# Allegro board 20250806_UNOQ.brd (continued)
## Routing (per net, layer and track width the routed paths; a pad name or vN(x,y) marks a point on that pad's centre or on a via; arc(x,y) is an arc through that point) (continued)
FORCED_USB_BOOT_POL_SEL: length 22.1
  TOP w0.066: R1313.2 R1314.1 22.21,17.64 21.45,18.4 21.45,27.13 21.18,27.4 21.18,28.5 20.77,28.91 20.77,30.77 v2(20.61,30.93)
  S3 w0.064: v2(20.61,30.93) 21.12,30.42 21.51,30.42 22.26,29.67 25.81,29.67 26.01,29.87 26.38,29.87 v2(26.57,29.68)
HPH_L: length 22.8
  TOP w0.15: v2(42.67,16.02) 42.63,15.98 PMIC1.L27
  S3 w0.15: v3(42.39,15.99) 42.65,15.99 v2(42.67,16.02)
  S6 w0.15: v5(42.4,16.3) 42.39,16.29 v3(42.39,15.99)
  BOTTOM w0.15: v5(42.4,16.3) 42.1,16.6 39.15,16.6 38.51,15.96 36.2,15.96 35.52,16.64 33.26,16.64 32.57,15.95 23.61,15.95 23.27,15.61 R2634.2
HPH_L_CONN: length 2.4
  BOTTOM w0.15: R2634.1 23.24,14.25 D26089.2 23.24,13.26 23.49,13 23.49,11.98
HPH_R: length 23.4
  TOP w0.15: v2(42.67,17.07) 42.39,17.07 41.87,16.55 PMIC1.J27
  S3 w0.15: v3(42.37,17.07) 42.67,17.07 v2(42.67,17.07)
  S6 w0.15: v3(42.37,17.07) v5(42.05,17.07)
  BOTTOM w0.15: R2635.2 22.73,15.66 23.38,16.31 32.47,16.31 33.14,16.98 35.6,16.98 36.39,16.19 38.33,16.19 39.02,16.88 41.86,16.88 v5(42.05,17.07)
HPH_R_CONN: length 2.5
  BOTTOM w0.15: 22.22,11.98 22.22,12.75 22.73,13.26 D26090.2 22.73,14.27 R2635.1
HPH_REF: length 27.4
  TOP w0.15: 42.12,16.26 PMIC1.K26
  TOP w0.2: v2(42.67,16.54) 42.4,16.54 42.12,16.26
  S3 w0.2: v2(42.67,16.54) 42.92,16.54 42.93,16.54 v3(42.95,16.54)
  S6 w0.2: v5(42.65,16.54) v3(42.95,16.54)
  BOTTOM w0.2: R2633.2 22,14.59 22,15.98 22.99,16.97 29.66,16.97 30.71,18.02 35.19,18.02 36.67,16.54 38.19,16.54 39.3,17.65 41.8,17.65 ; v5(42.65,16.54) 42.65,17.15
  BOTTOM w0.203: 42.65,17.15 42.15,17.65 41.8,17.65
HPH_REF_CONN: length 2.1
  BOTTOM w0.203: 20.95,11.98 20.95,12.66 21.68,13.39 R2633.1
HS_DET: length 51.5
  TOP w0.1: v2(22.42,8.72) 22.42,7.96 23.05,7.33 47.78,7.33 48.11,7.66 48.11,18.8 46.98,19.93 43.9,19.93 v2(43.81,20.02)
  S3 w0.064: v2(22.42,8.72) v3(22.42,9.16)
  S3 w0.1: v2(43.81,20.02) 43.56,19.76 42.75,19.76 42.09,19.1 41.2,19.1 40.39,18.29 40.39,18.21 v2(40.36,18.19)
  S6 w0.1: v3(22.42,9.16) 19.76,11.82 v5(19.68,11.82)
  BOTTOM w0.1: 19.68,11.98 v5(19.68,11.82)
JTAG_PS_HOLD: length 22
  TOP w0.066: v2(22.79,8.38) 35.02,8.38 R709.2
  S3 w0.064: v3(20.4,2.8) 20.12,3.08 20.12,5.5 22.79,8.17 v2(22.79,8.38)
  S6 w0.064: v5(21.71,2.8) v3(20.4,2.8)
  BOTTOM w0.066: TP1213.1 22.64,2.14 22.37,2.14 v5(21.71,2.8)
LDO1_EN: length 2
  BOTTOM w0.066: SB2801.2 11.68,39.33 R2801.2 11.7,40.05 U2801.1
LDO1_FB: length 3
  BOTTOM w0.203: U2801.6 13.6,41.08 12.83,40.31 R2803.1 13.3,40.01 R2802.2 13.42,40.01 C2803.2
LDO1_PG: length 8.2
  BOTTOM w0.203: U2801.5 14.43,42.32 15.11,42.32 15.11,42.09 15.94,41.26 C2808.1 17.08,41.26 R2810.1 17.44,41.37 17.58,41.51 17.58,44.86 Q2802.1
LDO2_EN: length 1
  BOTTOM w0.066: R2804.2 10.5,32.46 10.52,32.48 U2802.1
LDO2_FB: length 2.8
  BOTTOM w0.066: R2805.2 12.22,31.43 C2807.2 12.23,31.45 R2806.1 12.23,32.7 12.69,33.15 U2802.6
LED_MATRIX_0: length 22.5
  S3 w0.1: v3(13.22,9.1) 15.04,9.1 16.42,7.72 19.01,7.72 v2(19.03,7.74)
  S6 w0.1: v3(13.22,9.1) 13.18,9.14 13.18,9.63 9.32,13.49 9.32,15.95 12.04,18.67 12.04,21.34 v4(12.09,21.39)
  G7 w0.1: v4(12.09,21.39) 12.17,21.39 v5(12.9,22.11)
LED_MATRIX_0_R: length 84
  TOP w0.1: D27091.1 v1(8,10.77) ; v1(8.36,20.36) 8.63,20.36 D27074.2 9.88,21.05 v1(10.04,21.05) ; v1(10.91,26.39) 11.07,26.39 D27057.1 12.91,28.22 D27044.2 13.42,29 ; D27092.2 5.79,37.77 16.02,37.77 D27014.2 17.95,36.89 19.48,35.36 ; 15.39,26.86 15.39,27.03 13.42,29 ; 15.39,26.86 v1(14.91,26.39) ; 15.39,26.86 15.88,27.35 v1(16.04,27.35) ; v1(20.04,10.55) 19.03,9.54 R2711.2 ; 19.48,35.36 D27002.2 ; 19.48,35.36 19.88,35.75 v1(20.04,35.75) ; D27007.1 19.88,23.15 D27008.2 18.91,21.92 D27021.1 17.07,20.09 D27022.2 ; 13.42,29 13.88,29.45 D27043.1 ; v1(18.53,29.88) 18.91,30.26 D27004.2 19.07,30.59 D27003.1
  G2 w0.1: v1(10.04,21.05) 9.47,21.62 9.47,25.41 10.45,26.39 v1(10.91,26.39) ; v1(20.42,31.56) 20.42,35.37 v1(20.04,35.75) ; v1(18.53,29.88) 16.04,27.39 v1(16.04,27.35) ; v1(16.51,20.09) 13.58,23.02 13.58,25.29 14.68,26.39 v1(14.91,26.39) ; v1(8.36,20.36) 6.31,18.31 6.31,12.4 D27091.1 v1(8,10.77) 8.23,11 11.92,11 12.67,10.25 16.48,10.25 16.78,10.55 v1(20.04,10.55)
LED_MATRIX_1: length 25.9
  S3 w0.1: v2(21.85,7.96) 21.25,7.36 16.17,7.36 15.02,8.51 v3(13.77,8.51)
  S6 w0.1: v3(13.77,8.51) 13.77,9.35 9.55,13.56 9.55,15.72 12.29,18.47 12.29,20.8 12.42,20.93 12.42,22.59 v5(12.4,22.61)
LED_MATRIX_1_R: length 74.8
  TOP w0.1: v1(20.04,33.65) D27015.1 17.88,33.65 v1(16.91,32.69) ; v1(14.8,25.06) 14.23,25.06 D27045.1 13.53,24.74 ; v1(18.37,25.85) D27006.2 19.07,26.39 D27005.1 ; v1(10.91,22.19) 11.07,22.19 D27059.1 12.04,23.42 D27046.2 13.07,24.29 13.53,24.74 ; 13.53,24.74 15.51,22.76 15.51,22.63 ; 15.51,22.63 15.07,22.19 D27034.2 ; 15.51,22.63 v1(16.04,23.15) ; v1(20.59,17.83) 20.59,18.4 D27009.1 19.07,17.99 D27010.2 18.04,17.12 D27023.1 17.07,15.89 v1(16.91,15.89) ; v1(10.04,16.85) 9.07,15.89 D27076.2 ; D27094.2 5.88,33.65 D27093.1 6.04,33.65 v1(6.33,33.65)
  G2 w0.1: v1(14.8,25.06) 15.08,25.34 17.19,25.34 17.7,25.85 v1(18.37,25.85) ; v1(10.91,22.19) 10.91,21.07 10.39,20.55 10.39,17.2 v1(10.04,16.85) ; v1(18.91,36.89) 18.91,35.64 20.04,34.51 v1(20.04,33.65) 20.04,27.73 v1(20.4,27.37) ; v1(20.59,17.83) 21.16,17.83 21.85,17.14 v1(21.85,8.92) ; v1(16.91,32.69) 15.74,32.69 15.39,33.04 12.75,33.04 10.44,35.35 8.79,35.35 7.09,33.65 v1(6.33,33.65) ; v1(16.04,23.15) 16.04,20.91 16.8,20.15 16.8,18.86 16.44,18.5 16.44,16.35 v1(16.91,15.89)
LED_MATRIX_2: length 26.1
  S3 w0.1: v2(20.89,7.99) 20.44,7.54 16.3,7.54 15.03,8.81 12.94,8.81 12.73,9.02 v3(12.52,9.02)
  S6 w0.1: v5(12.4,23.11) 12.4,22.97 12.19,22.76 12.19,21.89 11.81,21.51 11.81,20.33 11.79,20.31 11.79,18.8 9.07,16.08 9.07,13.41 12.52,9.96 v3(12.52,9.02)
LED_MATRIX_2_R: length 84
  TOP w0.1: v1(6.45,29.04) D27095.1 5.07,28.49 D27096.2 ; D27011.1 19.07,13.79 D27012.2 18.04,12.92 D27025.1 17.07,11.69 v1(16.91,11.69) ; D27011.1 21.14,15.85 21.14,24.15 D27006.1 20.83,26.04 20.83,28.17 20.04,28.96 D27004.1 19.88,29.45 D27005.2 18.04,29.35 D27017.1 ; D27011.1 21.15,13.64 21.15,9.21 R2702.2 ; D27017.1 17.07,28.49 D27018.2 ; D27017.1 18.04,30.61 18.91,31.48 D27003.2 ; 15.47,18.55 D27036.2 ; 15.47,18.55 15.44,18.55 13.41,20.58 ; 15.47,18.55 15.88,18.95 D27035.1 ; 13.41,20.58 13.88,21.05 D27047.1 ; 13.41,20.58 D27048.2 12.91,19.82 D27061.1 11.88,18.95 v1(10.91,17.99) ; v1(10.04,12.23) D27077.1
  G2 w0.1: v1(10.04,12.23) 10.04,11.55 10.31,11.28 ; v1(6.45,29.04) 7.34,28.15 7.34,22.71 8.91,21.14 8.91,20.39 7.6,19.07 7.6,14.67 9.21,13.06 10.33,13.06 10.91,12.48 ; 12.11,11.28 12.78,10.61 15.31,10.61 16.39,11.69 v1(16.91,11.69) ; 12.11,11.28 10.91,12.48 ; 12.11,11.28 10.31,11.28 ; 10.31,11.28 9.31,11.28 v1(8.91,11.69) ; 10.91,12.48 v1(10.91,17.99)
LED_MATRIX_3: length 28.1
  S3 w0.1: v2(19.95,7.99) 18.46,7.99 18.09,8.36 16.69,8.36 15.19,9.86 12.89,9.86 11.45,11.3 8.46,11.3 v3(8.32,11.16)
  S6 w0.1: v3(8.32,11.16) 8.05,11.43 8.05,12.5 7.85,12.7 7.85,17.04 9.86,19.05 9.86,21.59 11.21,22.94 11.21,23.26 11.35,23.4 v4(11.35,23.47)
  G7 w0.1: v4(11.35,23.47) 11.49,23.61 11.9,23.61 12.04,23.47 12.04,23.45 v5(12.06,23.45)
  BOTTOM w0.1: v5(12.06,23.45) 12.04,23.45 12.04,23.47 MCU1.G5
LED_MATRIX_3_R: length 75.7
  TOP w0.1: D27027.1 15.88,35.75 v1(14.91,34.79) ; D27009.2 19.88,21.05 D27008.1 ; D27008.1 20.8,21.81 20.8,23.62 20.13,24.29 D27007.2 18.04,25.15 D27019.1 ; D27008.1 20.84,20.25 20.84,17.65 D27010.1 19.07,15.89 v1(18.91,15.89) ; D27020.2 17.88,25.25 D27019.1 ; D27098.2 5.07,24.29 v1(6.04,25.25) ; D27019.1 v1(18.84,25.25) ; v1(16.04,14.75) 15.88,14.75 D27038.2 14.91,14.9 13.42,16.39 ; v1(8.04,35.75) 7.88,35.75 D27080.2 ; 13.42,16.39 13.88,16.85 D27049.1 ; 13.42,16.39 D27050.2 12.04,15.02 D27063.1 11.07,13.79 D27064.2 ; R2703.2 19.95,9.03 20.82,9.9 20.82,11.87 v1(20.04,12.65)
  G2 w0.1: v1(6.04,25.25) 6.04,29.25 6.92,30.13 6.92,31.31 5.86,32.37 5.86,34.12 7.49,35.75 v1(8.04,35.75) 10.93,35.75 11.89,34.79 v1(14.91,34.79) 15.26,34.43 16.98,34.43 17.71,33.7 17.71,31.29 19.17,29.83 19.17,25.58 v1(18.84,25.25) ; v1(18.91,15.89) 20.04,14.75 v1(20.04,12.65) 19.03,12.65 16.93,14.75 v1(16.04,14.75)
LED_MATRIX_4: length 24.1
  S3 w0.1: v2(17.21,8.13) 16.61,8.13 15.1,9.64 12.83,9.64 11.43,11.04 10.13,11.04 v3(10.08,10.99)
  S6 w0.1: v5(11.9,24.11) 11.9,23.4 11.56,23.07 11.56,22.8 10.29,21.53 10.29,18.82 8.23,16.76 8.23,12.98 8.84,12.37 8.84,11.66 9.32,11.18 9.89,11.18 v3(10.08,10.99)
LED_MATRIX_4_R: length 81.2
  TOP w0.1: D27018.1 17.88,27.35 ; 17.88,27.35 D27019.2 16.8,26.28 16.8,25.41 v1(17.15,25.06) ; 17.88,27.35 17.04,27.35 16.03,28.36 16.03,28.5 16.91,29.38 D27017.2 ; D27030.2 15.88,31.55 D27029.1 16.04,31.45 D27017.2 ; D27081.1 7.88,31.55 D27082.2 ; D27100.2 5.07,20.09 v1(6.04,21.05) ; 13.54,12.15 D27051.1 ; 13.54,12.15 13.07,11.69 D27052.2 12.04,10.82 D27065.1 ; 13.54,12.15 15.14,10.55 v1(16.04,10.55) 17.21,9.38 R2704.2 ; D27017.2 17.88,31.55 v1(18.04,31.55) ; v1(18.04,35.75) 17.88,35.75 D27015.2
  G2 w0.1: v1(6.04,21.05) 5.76,21.33 5.76,29.77 v1(6.57,30.58) 6.57,30.92 5.51,31.98 5.51,35.14 7.65,37.28 v1(8.9,37.28) 8.92,37.26 v1(12.92,37.26) 15.58,37.26 17.09,35.75 v1(18.04,35.75) 18.51,35.28 18.51,32.02 v1(18.04,31.55) ; v1(17.15,25.06) 18.04,24.17 v1(18.04,23.15) 18.04,22.88 16.66,21.5 16.66,20.69 17.03,20.32 17.03,18.7 16.62,18.29 16.62,16.59 17.19,16.02 18.39,16.02 18.65,16.28 19.32,16.28 20.56,15.04 20.56,12.49 19.76,11.69 v1(18.91,11.69) 18.5,11.28 16.77,11.28 v1(16.04,10.55)
LED_MATRIX_5: length 28.1
  S3 w0.1: v3(10.01,9.73) 10.01,9.92 10.4,10.31 11.86,10.31 12.76,9.41 15,9.41 16.51,7.9 17.99,7.9 v2(18.08,7.99)
  S6 w0.1: v3(10.01,9.73) 10.01,10.24 9.45,10.8 7.66,10.8 7.24,11.22 7.24,12.65 7.47,12.88 7.47,17.22 9.47,19.23 9.47,21.77 10.67,22.96 10.67,23.22 10.67,23.22 10.67,23.27 10.82,23.42 10.87,23.42 v4(10.95,23.5)
  G7 w0.1: v5(11.9,23.11) 11.74,23.27 11.18,23.27 v4(10.95,23.5)
LED_MATRIX_5_R: length 65.9
  TOP w0.1: R2705.2 18.08,10.51 D27026.1 17.99,10.6 v1(17.99,11.7) ; 17.5,14.21 17.07,13.79 v1(16.91,13.79) ; 17.5,14.21 16.15,15.56 16.15,16.05 16.91,16.81 D27023.2 17.07,17.99 17.5,18.42 ; 17.5,14.21 D27024.1 ; D27042.2 13.07,32.69 D27041.1 14.04,33.55 v1(14.91,32.69) 15.07,32.69 D27028.1 16.04,34.69 v1(15.78,34.95) ; v1(8.04,27.35) 7.88,27.35 v1(6.91,26.39) ; v1(12.04,35.75) 11.88,35.75 D27054.2 10.91,34.52 D27067.1 9.88,33.65 v1(8.91,32.69) ; 17.5,18.42 D27022.1 ; 17.5,18.42 17.5,18.5 16.11,19.89 16.11,20.19 16.91,20.99 D27021.2 16.91,22.81 v1(17.02,22.91) ; v1(6.04,16.85) 5.88,16.85 D27102.2
  G2 w0.1: v1(8.91,32.69) 8.91,31.5 8.3,30.89 8.3,27.61 v1(8.04,27.35) ; v1(15.78,34.95) 14.91,35.82 v1(14.91,36.89) 14.06,36.89 12.92,35.75 v1(12.04,35.75) ; v1(6.91,26.39) 6.54,26.02 6.54,19.08 6.04,18.58 v1(6.04,16.85) ; v1(17.99,11.7) 17.93,11.7 16.91,12.72 v1(16.91,13.79) ; v1(14.91,32.69) 14.91,31.65 16.04,30.52 v1(16.04,29.45) 15.48,28.89 15.48,26.37 14.29,25.18 14.29,24.51 15.01,23.79 16.14,23.79 v1(17.02,22.91)
LED_MATRIX_6: length 22
  S3 w0.1: v2(7.87,7.76) 8.14,7.49 9.81,7.49 10.59,8.27 v3(10.59,9.92)
  S6 w0.1: v3(10.59,9.92) 10.59,10.01 9.63,10.97 8.99,10.97 8.51,11.46 8.51,12.4 8.03,12.88 8.03,16.89 10.06,18.92 10.06,21.55 11.38,22.87 11.38,23.14 11.63,23.39 11.63,23.88 v5(11.4,24.11)
LED_MATRIX_6_R: length 67.8
  TOP w0.1: D27086.2 7.88,23.15 v1(8.04,23.15) ; v1(17.12,10.09) 17.12,10.49 15.92,11.69 D27039.2 15.88,12.65 v1(16.04,12.65) ; D27033.2 15.07,24.29 15.54,24.75 ; v1(14.91,20.09) 15.88,21.05 D27034.1 16.04,22.26 16.8,23.02 16.8,23.49 15.54,24.75 ; R2706.2 7.02,9.57 5.89,9.57 4.91,10.55 D27104.2 5.88,12.65 v1(6.04,12.65) ; D27055.1 12.04,32.75 12.84,33.55 12.84,34.72 D27041.2 13.88,35.75 D27040.1 ; D27055.1 11.07,30.59 D27056.2 10.04,29.72 D27069.1 9.07,28.49 v1(8.91,28.49) ; D27055.1 D27042.1 14.04,30.43 14.91,29.56 v1(14.91,28.49) ; 15.54,24.75 15.54,24.83 v1(14.04,26.33) ; 15.54,24.75 D27032.1 ; v1(14.91,15.89) 15.07,15.89 D27036.1
  G2 w0.1: v1(17.12,10.09) 12.22,10.09 11.55,10.76 8.38,10.76 8.04,10.42 7.77,10.42 6.04,12.15 v1(6.04,12.65) ; v1(8.91,28.49) 8.91,26.84 8.04,25.97 v1(8.04,23.15) ; v1(14.04,26.33) 14.91,27.2 v1(14.91,28.49) ; v1(16.04,12.65) 14.91,13.79 v1(14.91,15.89) v1(14.91,20.09)
LED_MATRIX_7: length 18.1
  S3 w0.1: v2(11.34,7.76) 11.97,8.39 11.97,9.86 11.79,10.04 11.27,10.04 v3(11.18,9.95)
  S6 w0.1: v3(11.18,9.95) 11.18,10.71 8.66,13.23 8.66,16.48 10.74,18.57 10.74,21.41 11.44,22.11 v4(11.56,22.11)
  G7 w0.1: v5(11.9,22.11) v4(11.56,22.11)
LED_MATRIX_7_R: length 53.4
  TOP w0.1: D27043.2 12.04,29.72 v1(12.04,29.45) ; D27088.2 7.88,18.95 v1(8.04,18.95) ; D27048.1 13.07,17.99 v1(12.91,17.99) ; v1(10.91,32.69) 11.07,32.69 D27054.1 ; D27050.1 13.07,13.79 v1(12.91,13.79) ; v1(12.91,22.19) 13.88,23.15 D27046.1 ; D27052.1 13.17,10.55 R2707.2 ; v1(14.04,27.35) 13.88,27.35 D27045.2 ; v1(10.04,25.25) 9.88,25.25 v1(8.91,24.29) ; v1(10.02,34.88) 10.91,35.77 D27053.2
  G2 w0.1: v1(10.04,25.25) 10.9,25.25 ; 10.9,25.25 12.91,23.25 v1(12.91,22.19) v1(12.91,17.99) v1(12.91,13.79) 12.91,12.47 14.04,11.34 v1(14.04,10.94) ; 10.9,25.25 12.93,27.28 12.93,27.55 ; 12.93,27.55 13.13,27.35 v1(14.04,27.35) ; 12.93,27.55 12.04,28.44 v1(12.04,29.45) 12.04,30.6 10.91,31.73 v1(10.91,32.69) 10.02,33.58 v1(10.02,34.88) ; v1(8.91,24.29) 8.91,21.74 9.26,21.39 9.26,20.17 v1(8.04,18.95)
LED_MATRIX_8: length 17.3
  S3 w0.1: v2(10.48,7.78) 11.55,8.85 v3(11.55,9.6)
  S6 w0.1: v3(11.55,9.6) 11.55,10.65 8.86,13.34 8.86,16.26 11.05,18.44 11.05,20.8 11.38,21.13 v4(11.51,21.13)
  G7 w0.1: v5(12.27,21.13) v4(11.51,21.13)
  BOTTOM w0.1: MCU1.F1 v5(12.27,21.13)
LED_MATRIX_8_R: length 47.1
  TOP w0.1: 11.49,24.7 11.07,24.29 D27059.2 10.04,23.42 D27072.1 10.04,22.01 11.52,20.53 ; 11.49,24.7 D27058.1 ; 11.49,24.7 11.49,24.83 9.43,26.89 9.43,26.91 ; 9.43,31.11 8.03,32.51 8.03,32.68 8.91,33.56 D27067.2 9.07,34.79 D27066.1 ; 9.43,31.11 9.88,31.55 D27068.1 ; 9.43,31.11 D27069.2 8.91,29.33 8.14,28.56 8.14,28.2 9.43,26.91 ; 11.51,12.13 10.1,13.54 10.1,13.87 10.91,14.68 D27063.2 11.88,16.85 v1(12.04,16.85) ; 11.51,12.13 D27064.1 ; 11.51,12.13 11.07,11.69 v1(10.91,11.69) 10.91,9.17 R2708.2 ; 11.52,20.53 11.07,20.09 v1(10.91,20.09) ; 11.52,20.53 D27060.1 ; 9.43,26.91 D27071.2 ; 9.43,26.91 9.88,27.35 D27070.1 10.91,28.22 D27057.2 ; v1(6.91,13.79) 7.88,14.75 D27089.1
  G2 w0.1: v1(10.91,11.69) 10.05,12.55 8.15,12.55 v1(6.91,13.79) ; v1(10.91,20.09) 10.91,19.06 12.04,17.93 v1(12.04,16.85)
LED_MATRIX_9: length 17.9
  S3 w0.1: v3(10.5,10.65) 10.15,10.65 9.65,10.15 9.65,7.88 v2(9.55,7.78)
  S6 w0.1: v5(11.76,22.53) 11.61,22.53 10.52,21.44 10.52,18.73 8.43,16.65 8.43,13.13 9.63,11.94 9.7,11.94 10.5,11.14 v3(10.5,10.65)
  BOTTOM w0.1: MCU1.G3 11.82,22.53 v5(11.76,22.53)
LED_MATRIX_9_R: length 44
  TOP w0.1: R2709.2 10.04,9.23 D27078.1 10.04,11.51 8.51,13.04 8.51,13.12 ; 7.42,20.59 7.88,21.05 D27086.1 8.04,21.32 D27073.2 8.91,23.15 8.04,24.02 D27084.1 7.88,25.25 7.46,24.84 ; 7.42,20.59 9.46,18.55 9.46,18.53 ; 7.42,20.59 D27087.2 ; 9.46,18.53 D27075.2 8.91,17.72 D27088.1 7.07,15.89 v1(6.91,15.89) ; 9.46,18.53 9.88,18.95 D27074.1 ; 7.54,28.95 7.07,28.49 D27083.2 6.91,27.29 6.08,26.46 6.08,26.18 7.42,24.84 7.46,24.84 ; 7.54,28.95 7.49,28.95 6.08,30.36 6.08,30.73 6.91,31.56 D27081.2 7.07,32.69 7.51,33.13 ; 7.54,28.95 D27082.1 ; 8.51,13.12 v1(8.51,13.23) 8.91,13.64 D27077.2 9.88,14.75 D27076.1 ; 8.51,13.12 D27090.1 ; 7.46,24.84 D27085.2 ; 7.51,33.13 6.16,34.48 6.16,34.92 6.91,35.67 D27079.2 ; 7.51,33.13 D27080.1
  G2 w0.1: v1(8.51,13.23) 6.91,14.83 v1(6.91,15.89)
LED_MATRIX_10: length 18.1
  S3 w0.1: v3(7.79,11.14) 7.79,9.95 8.69,9.05 v2(8.69,7.77)
  S6 w0.1: v3(7.79,11.14) 7.65,11.28 7.65,17.12 9.65,19.13 9.65,21.67 10.92,22.94 v4(10.92,23.16)
  G7 w0.1: v4(10.92,23.16) 10.97,23.11 11.34,23.11 v5(11.5,22.95)
  BOTTOM w0.1: v5(11.5,22.95) 11.4,23.05 MCU1.H4
LED_MATRIX_10_R: length 38.1
  TOP w0.1: D27094.1 5.88,31.55 v1(4.91,30.59) ; 5.54,14.25 5.07,13.79 v1(4.91,13.79) ; 5.54,14.25 5.54,14.16 6.8,12.9 D27091.2 6.04,11.14 D27104.1 6.87,10.55 R2710.2 ; 5.54,14.25 D27102.1 ; v1(4.91,22.19) 5.07,22.19 D27098.1 ; D27092.1 5.07,34.79 v1(4.91,34.79) ; D27096.1 5.07,26.39 v1(4.91,26.39) ; v1(4.91,17.99) 5.07,17.99 D27100.1
  G2 w0.1: v1(4.91,34.79) v1(4.91,30.59) v1(4.91,26.39) v1(4.91,22.19) v1(4.91,17.99) v1(4.91,13.79)
LED_MATRIX_11: length 2.4
  BOTTOM w0.051: 8.61,23.85 9.16,23.85 MCU1.M5
  BOTTOM w0.1: 8.61,23.85 7.84,23.08 TP2506.1
LED_PWR: length 2.2
  TOP w0.254: D27201.1 29.81,65.61 R2735.2
LINEOUT_M: length 2.3
  BOTTOM w0.254: C514.1 26.76,15.31 25.19,15.31 25.02,15.14 R2632.2
LINEOUT_M_C: length 26.9
  S3 w0.15: v2(40.67,17.96) 40.68,17.95 41,17.95 41.25,18.2 41.89,18.2 42.95,19.25 45,19.25 v3(45.23,19.02)
  S6 w0.15: v5(45.53,19.04) 45.49,19.08 45.29,19.08 v3(45.23,19.02)
  BOTTOM w0.254: v5(45.53,19.04) 45.9,18.67 45.9,17.42 45.08,16.6 44.6,16.6 43.85,15.85 39.1,15.85 38.19,14.94 33.91,14.94 33.64,15.21 27.51,15.21 C514.2
LINEOUT_M_CONN: length 2.5
  BOTTOM w0.254: R2632.1 25.02,14.37 D26088.2 25.02,13.26 24.76,13.01 24.76,11.98
LINEOUT_P: length 1.2
  BOTTOM w0.254: R2631.2 26.46,14.88 26.73,14.61 C513.1
LINEOUT_P_C: length 28
  S3 w0.15: v3(45.56,19.45) 45.5,19.51 42.77,19.51 41.74,18.48 41.17,18.48 40.95,18.26 v2(40.95,18.24)
  S6 w0.15: v3(45.56,19.45) 45.62,19.51 45.81,19.51 v5(45.85,19.47)
  BOTTOM w0.254: C513.2 27.71,14.61 27.98,14.88 33.48,14.88 33.77,14.6 38.33,14.6 39.23,15.5 43.98,15.5 44.74,16.26 45.21,16.26 46.24,17.29 46.24,18.83 45.85,19.22 v5(45.85,19.47)
LINEOUT_P_CONN: length 2.5
  BOTTOM w0.254: 26.03,11.98 26.03,13.12 25.84,13.31 D26087.2 25.84,14.37 R2631.1
LNBBCLK1: length 6.8
  S3 w0.064: v2(30.3,13.56) 30.49,13.56 30.6,13.45 30.72,13.45 31.5,12.67 32.72,12.67 32.72,12.66 33.53,12.66 33.86,12.99 33.86,13.94 34.77,14.86 35.26,14.86 v2(35.28,14.88)
LNBBCLK2: length 6.1
  S3 w0.064: v2(34.65,14.28) 34.65,13.87 34.48,13.7 34.48,12.86 34.35,12.73 33.82,12.2 31.08,12.2 30.76,12.52 v2(30.28,12.52)
LNBBCLK2_R: length 0.5
  TOP w0.066: R703.1 C720.1
MCU_BOOT0: length 39.8
  S3 w0.064: v3(18.96,35.51) 14.86,35.51 14.55,35.82 13.8,35.82 v3(13.55,35.58)
  S6 w0.064: v5(6.31,42.62) 6.58,42.35 6.58,41.79 v5(6.49,41.7) ; v4(12.89,25.13) 12.89,25.87 11.96,26.8 11.96,32.8 13.55,34.39 v3(13.55,35.58) 13.55,35.87 v5(13.54,35.88) ; v3(18.96,35.51) 18.79,35.68 18.79,36.01 v5(19.07,36.29)
  G7 w0.064: v5(13.9,23.61) 13.67,23.85 13.67,24.36 v4(12.89,25.13)
  BOTTOM w0.066: v5(19.07,36.29) 19.1,36.29 19.24,36.43 19.24,36.69 18.21,37.72 U1101.10 ; JANALOG1.1 3.6,41.7 v5(6.49,41.7) 7.72,41.7 10.21,39.2 10.7,39.2 11.53,38.37 12.87,38.37 13.54,37.7 v5(13.54,35.88) ; R2621.1 6.31,43.26 v5(6.31,42.62)
MCU_BOOT0_1P8V: length 12.7
  TOP w0.066: v2(23.72,40.23) 23.83,40.34 24.31,40.34 SOC1.AH1
  S3 w0.064: v2(23.72,40.23) 23.47,39.98 21.11,39.98 20.43,40.66 v3(20.23,40.66)
  S6 w0.064: v5(20,40.44) v3(20.23,40.66)
  BOTTOM w0.066: v5(20,40.44) 19.96,40.39 18.82,40.39 18.65,40.22 15.93,40.22 15.22,39.5 15.22,38.23 15.74,37.71 16.04,37.71 U1101.2
MCU_BT_UART_CTS_R: length 1.8
  TOP w0.064: R2906.2 4.74,61 U2901.14
MCU_BT_UART_RTS_R: length 5.2
  TOP w0.064: U2901.11 8.79,63.17 4.8,63.17 R2904.2
MCU_BT_UART_RX_R: length 7
  TOP w0.064: R2901.2 23.16,62.23 20.82,62.23 20.28,61.69 17.97,61.69 U2901.4
MCU_BT_UART_TX_R: length 2
  TOP w0.064: U2901.41 21.43,60.05 R2908.2
MCU_CRS_SYNC_PA10: length 59.2
  S6 w0.064: v4(4.67,26.49) 4.67,25.32 3.76,24.41 3.76,15.32 4.58,14.5 4.58,6.71 6.04,5.25 9.01,5.25 11.11,3.15 v5(15.1,3.15)
  G7 w0.064: v4(4.67,26.49) 5.69,27.51 6.91,27.51 7.39,27.03 7.87,27.03 8.05,26.85 12.16,26.85 v5(12.4,26.61)
  BOTTOM w0.066: JMISC1.25 29.84,6.63 29.6,6.39 24.73,6.39 23.38,5.04 23.38,4.04 23.23,3.89 15.84,3.89 v5(15.1,3.15)
MCU_I2C2_SCL: length 75.7
  S6 w0.064: v5(10.64,27.89) 10.64,28.34 9.07,29.91 9.07,45.77 8.14,46.7 8.14,53.28 v5(8.34,53.48)
  BOTTOM w0.051: 10.64,25.86 v5(10.64,27.89)
  BOTTOM w0.066: MCU1.K9 10.64,25.86 ; v5(8.34,53.48) 8.59,53.23 11.04,53.23 12.65,51.62 14.51,51.62 18.96,47.17 18.96,43.38 20.38,41.96 33.98,41.96 34.82,42.8 39.75,42.8 43.36,46.41 R2643.2 R2644.1
MCU_I2C2_SCL_CONN: length 10
  BOTTOM w0.066: R2644.2 47.32,46.41 47.68,46.05 51.71,46.05 52.2,46.53 52.2,48.82 51.24,49.78 JDIGITAL1.18
MCU_I2C2_SDA: length 76.4
  S6 w0.064: v5(7.9,53.59) 7.98,53.51 7.98,46.64 8.87,45.75 8.87,29.81 10.26,28.42 v5(10.26,27.94)
  BOTTOM w0.051: 10.13,26.01 10.13,27.81
  BOTTOM w0.066: 10.13,26.01 9.9,25.77 MCU1.L9 ; R2645.1 R2642.2 43.63,46.96 39.63,42.96 34.75,42.96 33.91,42.12 20.45,42.12 19.12,43.45 19.12,47.23 14.58,51.78 12.72,51.78 11.11,53.39 8.8,53.39 8.5,53.69 8,53.69 v5(7.9,53.59) ; 10.13,27.81 v5(10.26,27.94)
MCU_I2C2_SDA_CONN: length 4.3
  BOTTOM w0.066: R2645.2 50.52,46.96 JDIGITAL1.17
MCU_I2C4_SCL_PD12: length 43.9
  TOP w0.066: v2(7.62,7.02) 7.83,7.23 12.95,7.23 13.16,7.44 15.67,7.44 16.01,7.1 R2614.2 16,7.07 R2615.1
  S3 w0.064: v2(7.62,7.02) 5.68,7.02 4.57,5.91 3.86,5.91 3.35,6.42 1.48,6.42 1.07,6.83 1.07,18.28 3.15,20.36 v3(3.15,21.44)
  S6 w0.064: v3(3.15,21.44) 3.39,21.44 v4(3.48,21.35)
  G7 w0.064: v5(10.15,23.86) 9.84,23.86 9.58,23.6 8,23.6 7.75,23.34 4.93,23.34 4.67,23.09 4.67,22.38 3.64,21.35 v4(3.48,21.35)
  BOTTOM w0.051: v5(10.15,23.86) 10.58,23.86 10.67,23.95 10.67,25.27 10.57,25.37 10.21,25.37 10.15,25.43 10.15,25.74
  BOTTOM w0.066: MCU1.K10 10.4,25.99 10.15,25.74
MCU_I2C4_SCL_PD12_CONN: length 1.6
  TOP w0.066: QWIIC1.4 15.85,6.03 15.47,6.41 R2615.2
MCU_I2C4_SCL_PF14: length 52.5
  S3 w0.064: v6(3.3,14.2) 5.01,14.2 7.36,11.85 12.32,11.85 13.43,10.74 23.1,10.74 24.62,9.22 v3(25.35,9.22)
  S6 w0.064: v4(25.37,8.89) 25.37,9.19 v3(25.35,9.22)
  G7 w0.064: v5(35.82,13.54) 35.55,13.81 31.37,13.81 26.61,9.04 25.53,9.04 v4(25.37,8.89)
  BOTTOM w0.058: 8.58,24.36 9.65,24.36 MCU1.L6 ; 7.86,23.64 7.16,23.64 6.54,23.02 ; 4.49,21.89 4.49,15.05 3.63,14.2 v6(3.3,14.2)
  BOTTOM w0.066: 6.54,23.02 5.62,23.02 4.49,21.89 ; v5(35.82,13.54) R2668.1 ; 8.58,24.36 7.86,23.64
MCU_I2C4_SCL_PF14_CONN: length 1.8
  BOTTOM w0.066: R2668.2 36.85,13.38 36.19,12.72 36.19,11.98
MCU_I2C4_SDA_PD13: length 48.5
  TOP w0.066: 14.34,7.09 R2613.2 ; 14.34,7.09 14.21,7.22 13.21,7.22 13.05,7.06 10.56,7.06 v2(9.2,5.7) ; 14.34,7.09 R2616.1
  S3 w0.064: v3(2.97,26.67) 1.73,26.67 0.56,25.5 0.56,4.72 1.67,3.61 4.48,3.61 5.79,4.92 8.42,4.92 v2(9.2,5.7)
  S6 w0.064: v4(3.45,26.29) 3.07,26.67 v3(2.97,26.67)
  G7 w0.064: v5(10.4,27.11) 10.31,27.03 9.45,27.03 8.79,27.69 5.31,27.69 3.91,26.29 v4(3.45,26.29)
MCU_I2C4_SDA_PD13_CONN: length 1.5
  TOP w0.066: R2616.2 14.86,5.11 QWIIC1.3
MCU_I2C4_SDA_PF15: length 48.9
  S3 w0.064: v6(3.43,13.67) 5.29,13.67 7.29,11.67 12.25,11.67 13.35,10.57 23.08,10.57 24.86,8.79 v3(24.94,8.79)
  S6 w0.064: v3(24.94,8.79) 25.2,8.53 v4(25.37,8.53)
  G7 w0.064: v4(25.37,8.53) 26.41,8.53 31.42,13.54 v5(33.78,13.54)
  BOTTOM w0.058: 6.59,22.86 7.22,23.49 7.92,23.49 ; v6(3.43,13.67) 4.63,14.87 4.63,21.83
  BOTTOM w0.066: 4.63,21.83 5.67,22.86 6.59,22.86 ; MCU1.N6 8.54,24.11 7.92,23.49 ; R2669.1 v5(33.78,13.54)
MCU_I2C4_SDA_PF15_CONN: length 1.6
  BOTTOM w0.066: R2669.2 34.8,12.1 34.92,11.98
MCU_JTAG_NJTRST_PB4: length 77.2
  TOP w0.066: JDIGITAL1.9 49.5,25.62 49.5,6.91 48.74,6.15 24.66,6.15 23.31,4.8 20.79,4.8 v2(20.7,4.71)
  S3 w0.064: v2(20.7,4.71) 21.71,5.72 21.71,6.75 23.19,8.23 v3(23.19,9.64)
  S6 w0.064: v3(23.19,9.64) 23.19,10.59 20.04,13.74 v5(20.04,16.36)
  BOTTOM w0.066: v5(20.04,16.36) 20.04,22.99 18.9,24.13 TP2504.1 17.55,24.28 16.49,24.28 16.41,24.36 14.64,24.36 MCU1.B6
MCU_JTAG_SWCLK: length 24.2
  S3 w0.064: v3(19.25,35.18) 19.13,35.05 14.99,35.05 14.69,35.35 v3(14.25,35.35)
  S6 w0.064: v3(19.25,35.18) 19.41,35.33 19.41,36.69 19.16,36.94 v5(19.16,37.55) ; v3(14.25,35.35) 14.2,35.3 14.2,34.23 13.67,33.7 13.67,30.09 14.48,29.28 14.48,28.35 13.87,27.74 13.87,27.15 13.74,27.03 13.74,26.27 v5(13.9,26.11)
  BOTTOM w0.051: v5(13.9,26.11) 14.15,25.86 15.37,25.86
  BOTTOM w0.066: U1101.8 17.46,38.51 18.72,38.51 19.02,38.21 19.02,37.69 v5(19.16,37.55) ; 15.37,25.86 15.75,26.24 17.07,26.24 TP2503.1
MCU_JTAG_SWCLK_1P8V: length 13.3
  S3 w0.064: v2(26.57,39.28) 26.37,39.48 26.37,39.75 25.98,40.13 24.18,40.13 23.75,39.7 20.29,39.7 v3(20.14,39.85)
  S6 w0.064: v3(20.14,39.85) 20.04,39.95 v5(19.75,39.95)
  BOTTOM w0.066: U1101.4 16.04,38.51 15.76,38.51 15.54,38.73 15.54,39.3 16.09,39.85 18.95,39.85 19.05,39.95 v5(19.75,39.95)
MCU_JTAG_SWDIO: length 18.8
  S3 w0.064: v3(14.38,36.42) 14.59,36.63 17.11,36.63 17.75,35.99 19.05,35.99 v3(19.11,35.93)
  S6 w0.064: v3(14.38,36.42) 13.87,35.91 13.87,34.31 12.4,32.84 v5(12.4,27.11) ; v5(18.82,37.46) 19.03,37.25 19.03,36.88 19.28,36.63 19.28,36.18 19.11,36.01 v3(19.11,35.93)
  BOTTOM w0.066: U1101.9 17.96,38.12 18.06,38.02 TP2502.1 18.82,37.76 v5(18.82,37.46)
MCU_JTAG_SWDIO_1P8V: length 14
  S3 w0.064: v3(20.56,40.16) 20.88,39.84 23.68,39.84 24.13,40.28 26.06,40.28 26.57,39.78 v2(26.57,39.68)
  S6 w0.064: v5(20.24,40.25) 20.36,40.13 20.53,40.13 v3(20.56,40.16)
  BOTTOM w0.066: U1101.3 16.04,38.11 15.74,38.11 15.39,38.46 15.39,39.42 15.98,40.01 18.68,40.01 18.84,40.18 20.17,40.18 v5(20.24,40.25)
MCU_JTAG_SWO_PB3: length 77.1
  S3 w0.064: v3(16.43,1.75) 17.45,1.75 17.93,1.27 21.09,1.27 23.67,3.85 23.67,5.91 24.31,6.55 31.41,6.55 32.71,5.26 47.96,5.26 49.53,6.83 49.53,8.89 JDIGITAL1.3
  S6 w0.064: v3(16.43,1.75) 16.36,1.83 16.36,3.12 11.26,8.22 8.82,8.22 6.32,10.72 6.32,13.06 6.49,13.22 6.49,17.56 8.02,19.08 8.02,19.86 8.18,20.02 8.18,22.83 7.98,23.04 7.98,23.39 8.41,23.83 8.74,23.83 9.17,24.26 9.17,24.92 v4(8.99,25.1)
  G7 w0.064: v4(8.99,25.1) 11.46,25.1 11.67,24.89 12.62,24.89 v5(13.4,24.11)
MCU_JTAG_TDI: length 2.7
  BOTTOM w0.051: MCU1.A10 15.34,26.11
  BOTTOM w0.066: 15.34,26.11 15.7,26.47 17.2,26.47 TP2501.1
MCU_LED1_BLU: length 78.9
  G7 w0.064: v5(35.37,6.44) 34.82,6.44 34.38,6.88 24.14,6.88 23.02,5.76 23.02,3.35 21.14,1.47 12.61,1.47 8.85,5.23 5.62,5.23 4.28,3.89 1.78,3.89 1.28,4.4 1.28,28.41 2.13,29.26 3.45,29.26 3.63,29.44 7.77,29.44 8,29.21 9.56,29.21 9.61,29.16 10.44,29.16 v5(10.52,29.24)
  BOTTOM w0.058: MCU1.B13 14.4,27.97 13.51,28.85 12.12,28.85 11.68,29.29 10.57,29.29 v5(10.52,29.24)
MCU_LED1_BLU_D: length 12.3
  TOP w0.066: 46.4,3.98 46.4,4.07 45.65,4.82 40.69,4.82 40.33,4.46 37.64,4.46 v2(37.55,4.55)
  S3 w0.064: v3(37.25,4.55) v2(37.55,4.55)
  S6 w0.064: v5(36.51,4.85) 36.82,4.55 v3(37.25,4.55)
  BOTTOM w0.066: R2731.1 36.48,6.29 36.48,4.89 v5(36.51,4.85)
MCU_LED1_GRN: length 82.8
  G7 w0.064: v5(37.31,6.25) 37.31,6.21 37.03,5.93 35.07,5.93 34.25,6.74 24.2,6.74 23.16,5.7 23.16,3.29 21.2,1.33 12.56,1.33 8.8,5.09 5.68,5.09 4.34,3.76 1.73,3.76 1.14,4.34 1.14,28.67 v5(1.35,28.88) ; v5(11.46,28.52) 9.86,28.52 9.65,28.73 9.45,28.73 9.42,28.7 7.79,28.7 7.51,28.99 4.5,28.99 4.04,28.52 v5(3.58,28.52)
  BOTTOM w0.058: MCU1.D9 13.64,25.85 13.64,27.76 13,28.4 11.58,28.4 v5(11.46,28.52)
  BOTTOM w0.066: v5(3.58,28.52) 3.1,29.01 1.47,29.01 v5(1.35,28.88)
MCU_LED1_GRN_D: length 13
  TOP w0.066: 46.4,3.13 46.4,3.28 v2(46.92,3.8)
  S3 w0.064: v2(46.92,3.8) 46.83,3.89 44.22,3.89 44.02,3.69 43.21,3.69 42.8,4.1 41.03,4.1 40.79,3.86 38.16,3.86 v3(37.98,4.04)
  S6 w0.064: v5(38.27,3.9) 38.12,3.9 v3(37.98,4.04)
  BOTTOM w0.066: R2730.1 v5(38.27,3.9)
MCU_LED1_RED: length 83.6
  G7 w0.064: v5(3.81,28.78) 4.06,28.78 4.42,29.14 7.57,29.14 7.85,28.85 9.38,28.85 9.4,28.87 9.7,28.87 9.8,28.78 v5(11.1,28.78) ; v5(1.35,29.26) 1.35,29.24 1,28.89 1,4.28 1.67,3.62 4.42,3.62 5.74,4.94 8.73,4.94 12.49,1.18 21.26,1.18 23.31,3.23 23.31,5.64 24.26,6.59 34.19,6.59 35.06,5.72 38.59,5.72 v5(39.11,6.24)
  BOTTOM w0.058: v5(11.1,28.78) 11.66,28.78 11.88,28.56 13.27,28.56 13.9,27.94 MCU1.C13
  BOTTOM w0.066: v5(3.81,28.78) 3.73,28.85 3.48,28.85 3.17,29.16 1.44,29.16 1.35,29.25 v5(1.35,29.26)
MCU_LED1_RED_D: length 9
  TOP w0.066: D27401.2 45.55,4.36 45.23,4.68 40.75,4.68 40.39,4.32 38.59,4.32 38.55,4.28 v2(38.55,4.25)
  S3 w0.064: v3(38.69,4.54) 38.69,4.39 v2(38.55,4.25)
  S6 w0.064: v3(38.69,4.54) 38.69,4.59 v5(39.11,5.01)
  BOTTOM w0.066: R2729.1 v5(39.11,5.01)
MCU_LED2_BLU: length 90.4
  G7 w0.064: v5(39.66,5.73) 39.51,5.58 35.01,5.58 34.13,6.45 24.32,6.45 23.45,5.58 23.45,3.17 21.32,1.04 12.43,1.04 8.68,4.8 5.8,4.8 4.47,3.48 1.61,3.48 0.86,4.23 0.86,29.31 1.3,29.74 1.3,31.11 1.86,31.68 3.86,31.68 4.22,31.32 4.22,30.08 4.56,29.74 7.9,29.74 8.13,29.51 9.68,29.51 v5(9.73,29.57)
  BOTTOM w0.058: MCU1.A13 14.9,27.98 13.7,29.17 12.32,29.17 11.8,29.69 9.86,29.69 v5(9.73,29.57)
  BOTTOM w0.066: v5(39.66,5.73) 39.66,4.87 R2734.2
MCU_LED2_BLU_D: length 10.2
  TOP w0.066: v2(39.49,4.7) 39.91,5.12 47.06,5.12 48.2,3.98 D27402.3
  S3 w0.064: v2(39.49,4.7) 39.82,4.37 v3(39.84,4.37)
  S6 w0.064: v5(40.13,4.37) v3(39.84,4.37)
MCU_LED2_GRN: length 91.8
  G7 w0.064: v5(40.18,6.32) 40.18,5.86 39.76,5.44 34.95,5.44 34.08,6.31 24.38,6.31 23.59,5.52 23.59,3.11 21.38,0.9 12.38,0.9 8.62,4.66 5.85,4.66 4.53,3.34 1.55,3.34 0.73,4.17 0.73,29.37 1.16,29.8 1.16,31.21 1.83,31.88 v5(1.88,31.88) ; v5(10.19,29.44) 10.08,29.33 9.63,29.33 9.62,29.35 8.06,29.35 7.83,29.58 4.33,29.58 3.78,30.13 v5(3.78,31.34)
  BOTTOM w0.058: v5(10.19,29.44) 10.26,29.51 11.71,29.51 12.2,29.03 13.59,29.03 14.66,27.97 14.66,27.51 14.49,27.35 14.24,27.35 14.15,27.25 14.15,26.86 MCU1.C11
  BOTTOM w0.066: v5(1.88,31.88) 1.98,31.78 3.35,31.78 v5(3.78,31.34)
MCU_LED2_GRN_D: length 10.6
  TOP w0.066: v2(48.77,3.75) 48.3,3.28 D27402.4
  S3 w0.064: v2(48.77,3.75) 48.41,4.11 44,4.11 43.8,3.91 43.33,3.91 43.02,4.22 40.61,4.22 v3(40.56,4.27)
  S6 w0.064: v3(40.56,4.27) 40.25,4.58 v5(40.25,5.3)
MCU_LED2_RED: length 88
  G7 w0.064: v5(10.82,29.03) 10.74,28.96 10.46,28.96 10.41,29.01 7.92,29.01 7.63,29.29 4.36,29.29 4.25,29.18 v5(3.89,29.18) ; v5(0.83,29.75) 0.59,29.51 0.59,4.11 1.5,3.2 4.59,3.2 5.91,4.52 8.56,4.52 12.32,0.76 21.44,0.76 23.73,3.05 23.73,5.46 24.44,6.17 34.02,6.17 34.89,5.3 39.85,5.3 40.37,5.82 v5(41.03,5.82)
  BOTTOM w0.058: MCU1.C12 13.9,27.26 14.15,27.51 14.15,27.94 13.39,28.7 11.99,28.7 11.66,29.03 v5(10.82,29.03)
  BOTTOM w0.066: v5(3.89,29.18) 3.61,29.18 3.45,29.34 1.91,29.34 1.73,29.51 1.07,29.51 v5(0.83,29.75)
MCU_LED2_RED_D: length 8.9
  TOP w0.066: D27402.2 47.45,4.01 46.48,4.98 40.43,4.98 40.18,4.73 v2(40.18,4.68)
  S3 w0.064: v3(40.82,4.63) 40.72,4.73 40.23,4.73 v2(40.18,4.68)
  S6 w0.064: v3(40.82,4.63) 40.82,4.67 41,4.85 v5(41.03,4.85)
MCU_MCO_PA8: length 57.5
  S6 w0.064: v4(4.39,24.61) 3.91,24.13 3.91,15.39 4.7,14.6 4.7,6.81 6.11,5.4 9.07,5.4 11.13,3.35 15.53,3.35 v5(15.62,3.26)
  G7 w0.064: v4(4.39,24.61) 5.92,24.61 6.45,24.08 7.44,24.08 7.7,24.33 8.23,24.33 8.76,24.87 11.48,24.87 11.68,24.66 v5(11.89,24.66)
  BOTTOM w0.066: JMISC1.23 31.11,7.17 30.16,6.22 24.8,6.22 23.55,4.97 23.55,3.97 23.3,3.72 16.08,3.72 v5(15.62,3.26)
MCU_NRST: length 92.3
  TOP w0.066: v2(18.73,4.74) 19.06,4.41 20.73,4.41 20.98,4.66 25.16,4.66 JSPI1.5
  S3 w0.064: v3(19.46,34.72) 14.65,34.72 v3(14.51,34.86) ; v3(14,32.72) 7.26,32.72 v3(7.17,32.63) ; v3(2.5,20.47) 2.5,19.96 0.91,18.37 0.91,6.75 1.39,6.27 3.22,6.27 3.76,5.73 4.63,5.73 5.7,6.8 7.79,6.8 8.21,7.22 12.58,7.22 14.11,5.69 18.07,5.69 18.73,5.03 v2(18.73,4.74)
  S6 w0.064: v3(14,32.72) 14.42,33.14 14.42,34.77 v3(14.51,34.86) ; v4(4.88,22.91) 4.95,22.99 4.95,28.62 7.17,30.84 v3(7.17,32.63) 7.17,35.22 v5(6.2,36.19) ; v3(2.5,20.47) v4(3.48,20.47) ; v5(19.28,37.9) 19.36,37.82 19.36,36.97 19.66,36.67 19.66,34.92 v3(19.46,34.72)
  G7 w0.064: v5(11.4,22.61) 11.35,22.61 11.05,22.91 10.9,22.91 10.49,23.32 10.21,23.32 10.06,23.16 8.46,23.16 8.28,22.99 4.95,22.99 v4(4.88,22.91) 4.88,22.37 3.48,20.97 v4(3.48,20.47)
  BOTTOM w0.066: v5(19.28,37.9) 19.28,38.27 18.64,38.91 17.46,38.91 U1101.7 ; TP2602.1 6.65,36.53 6.65,36.52 R2622.2 v5(6.2,36.19) 5.57,35.56 JANALOG1.3
MCU_NRST_1P8V: length 9.2
  S3 w0.064: v2(24.57,39.68) 24.15,39.68 23.86,39.39 19.72,39.39 v3(19.55,39.56)
  S6 w0.064: v3(19.55,39.56) v5(19.26,39.56)
  BOTTOM w0.066: v5(19.26,39.56) 19.19,39.63 16.5,39.63 16.05,39.18 U1101.5
MCU_OPAMP1_ VINM_PA1: length 52.5
  S6 w0.064: v4(13.46,5.24) 13.27,5.24 12.54,5.97 9.5,5.97 9.36,6.11 6.4,6.11 5.36,7.15 5.36,15.05 4.7,15.71 4.7,19.84 5.28,20.42 5.28,21.46 v4(5.38,21.56)
  G7 w0.064: v5(9.9,22.61) 9.8,22.71 8.64,22.71 8.46,22.53 6.45,22.53 5.49,21.56 v4(5.38,21.56) ; v5(19.42,10.71) 19.54,10.59 19.54,8.48 19.18,8.12 19.18,6.18 18.35,5.35 13.57,5.35 v4(13.46,5.24)
  BOTTOM w0.066: v5(19.42,10.71) 19.64,10.93 21.58,10.93 21.71,10.79 30.68,10.79 31.11,11.22 31.11,11.98
MCU_OPAMP1_ VINP_PA0: length 55
  S6 w0.064: v4(13.66,5.04) 13.21,5.04 12.46,5.79 9.5,5.79 9.31,5.98 6.35,5.98 5.23,7.1 5.23,14.97 4.55,15.65 4.55,19.89 5.13,20.47 5.13,21.82 v4(5.25,21.93)
  G7 w0.064: v4(13.66,5.04) 13.77,5.15 18.44,5.15 19.38,6.09 19.38,8.03 19.74,8.39 19.74,10.51 v5(19.9,10.67) ; v4(5.25,21.93) 5.64,21.93 6.39,22.68 8.39,22.68 8.57,22.86 10.15,22.86 v5(10.4,22.61)
  BOTTOM w0.066: 32.38,11.98 32.38,10.88 32.12,10.62 21.62,10.62 21.52,10.72 19.95,10.72 v5(19.9,10.67)
MCU_OPAMP1_VOUT_PA3: length 52.4
  S6 w0.064: v4(13.38,5.6) 13.13,5.6 12.6,6.13 11.27,6.13 10.97,6.43 8.53,6.43 7.75,7.21 v5(6.04,7.21) ; v5(16.77,9.62) 16.95,9.44 16.95,6.04 v4(17.42,5.57)
  G7 w0.066: v4(13.38,5.6) 17.39,5.6 v4(17.42,5.57)
  BOTTOM w0.058: MCU1.N2 8.57,22.11 8.28,21.82 8.28,21.71 8.28,21.71 8.28,21.39 7.98,21.09 6.39,21.09 5.68,20.38
  BOTTOM w0.066: 5.68,20.38 5.68,10.3 6.04,9.94 v5(6.04,7.21) ; 33.65,11.98 33.65,10.79 33.3,10.44 18.56,10.44 18.21,10.09 17.24,10.09 v5(16.77,9.62)
MCU_OSC32_IN_PC14: length 1.7
  BOTTOM w0.066: R2514.2 14.07,20.3 13.4,20.97 MCU1.D1
MCU_OSC32_OUT_PC15: length 1.7
  BOTTOM w0.066: MCU1.E1 12.9,21.16 13.49,20.57 R2513.1
MCU_OSC_IN_PH0_R: length 1.6
  BOTTOM w0.066: R2509.1 10.59,20.81 MCU1.H1
MCU_OSC_OUT_PH1_R: length 1.6
  BOTTOM w0.066: R2511.1 10.06,20.55 10.9,21.39 MCU1.J1
MCU_PA4: length 8.9
  G7 w0.064: v5(6.1,20.17) v5(3.48,20.17)
  BOTTOM w0.058: v5(6.1,20.17) 6.74,20.81 8.15,20.81 8.9,21.56 MCU1.N1
  BOTTOM w0.066: JANALOG1.9 3.63,18.87 3.63,20.02 v5(3.48,20.17)
MCU_PA5: length 13.7
  G7 w0.064: v5(10.4,23.11) 10.3,23.01 8.51,23.01 8.33,22.83 5.66,22.83 4.03,21.2 v5(4.03,20.92)
  BOTTOM w0.066: JANALOG1.10 2.54,16.08 3.84,17.37 3.84,20.73 v5(4.03,20.92)
MCU_PA6: length 23.9
  BOTTOM w0.058: MCU1.N4 8.58,23.11 7.84,22.37 6.24,22.37 ; JANALOG1.11 2.54,12.47 0.97,10.9 0.97,9.68 1.84,8.81 3.02,8.81 3.78,9.58 3.78,11.68 4.95,12.85 4.95,21.08
  BOTTOM w0.066: 6.24,22.37 4.95,21.08
MCU_PA7: length 19
  BOTTOM w0.058: JANALOG1.12 2.54,10.64 4.81,12.91 4.81,21.17 ; MCU1.J5 10.63,23.34 8.61,23.34 7.79,22.52 6.16,22.52
  BOTTOM w0.066: 6.16,22.52 4.81,21.17
MCU_PA11: length 82.9
  S3 w0.064: v3(17.83,2.36) 18.39,1.81 20.87,1.81 23.13,4.07 23.13,6.13 24.09,7.09 31.64,7.09 32.93,5.79 47.64,5.79 49,7.15 49,15.98 JDIGITAL1.6
  S6 w0.064: v4(9.91,28.07) 9.46,27.62 9.46,24.15 9.45,24.14 9.45,24.08 8.61,23.24 8.61,21.9 9.14,21.36 9.14,19.37 7.09,17.31 7.09,12.98 6.92,12.81 6.92,10.81 8.91,8.82 11.5,8.82 17.83,2.49 v3(17.83,2.36)
  G7 w0.064: v4(9.91,28.07) 9.98,28.14 11.37,28.14 v5(11.9,27.61)
MCU_PA12: length 81.7
  S3 w0.064: JDIGITAL1.5 49.17,13.61 49.17,6.97 47.81,5.61 32.86,5.61 31.56,6.91 24.17,6.91 23.31,6.05 23.31,4 20.94,1.63 18.08,1.63 17.07,2.64 v3(16.97,2.64)
  S6 w0.064: v3(16.97,2.64) 16.97,2.93 11.38,8.52 8.86,8.52 6.62,10.76 6.62,12.93 6.79,13.1 6.79,17.43 8.31,18.96 8.31,19.74 8.47,19.9 8.47,23.3 8.48,23.31 8.48,23.37 9.32,24.21 9.32,27.94 v4(9.42,28.04)
  G7 w0.064: v5(12.4,27.61) 11.72,28.3 9.68,28.3 v4(9.42,28.04)
MCU_PB0: length 73.8
  S3 w0.064: JDIGITAL1.4 49.35,11.25 49.35,6.9 47.89,5.44 32.78,5.44 31.49,6.73 24.24,6.73 23.49,5.98 23.49,3.92 21.02,1.45 18.01,1.45 17.25,2.21 v3(16.69,2.21)
  S6 w0.064: v3(16.69,2.21) 16.61,2.29 16.61,3.07 11.32,8.37 8.84,8.37 6.47,10.74 6.47,13 6.64,13.17 6.64,17.5 8.16,19.02 8.16,19.8 8.33,19.97 8.33,23.16 v4(8.23,23.27)
  G7 w0.064: v5(10.4,23.61) 10.2,23.61 9.98,23.39 8.36,23.39 v4(8.23,23.27)
MCU_PB1: length 81.4
  S3 w0.064: v3(15.98,2.79) 16.18,3 17.11,3 17.42,2.69 18.02,2.69 18.73,1.98 20.8,1.98 22.96,4.14 22.96,6.2 24.02,7.26 31.71,7.26 33.01,5.97 47.52,5.97 48.82,7.27 48.82,18.34 JDIGITAL1.7
  S6 w0.064: v5(5.82,22.56) 5.84,22.53 5.94,22.53 6.2,22.28 6.2,20.5 5.33,19.63 5.33,16 6.15,15.19 6.15,10.71 8.78,8.08 11.2,8.08 15.98,3.3 v3(15.98,2.79)
  BOTTOM w0.058: 5.93,22.67 7.74,22.67 8.68,23.61
  BOTTOM w0.066: 8.68,23.61 MCU1.N5 ; v5(5.82,22.56) 5.93,22.67
MCU_PB2: length 80.7
  S3 w0.064: v3(17.83,3) 18.18,3 19.05,2.13 20.69,2.13 22.78,4.22 22.78,6.28 23.94,7.44 31.78,7.44 33.08,6.15 47.4,6.15 48.64,7.39 48.64,20.7 JDIGITAL1.8
  S6 w0.064: v3(17.83,3) 17.55,3 11.58,8.97 8.93,8.97 7.07,10.83 7.07,12.75 7.24,12.92 7.24,17.25 9.3,19.3 9.3,21.54 8.76,22.07 8.76,23.06 8.99,23.29 9.58,23.29 v5(9.9,23.61)
MCU_PB8: length 77.5
  TOP w0.066: v2(18.12,4.9) 18.19,4.97 23.24,4.97 24.59,6.32 48.69,6.32 49.34,6.97 49.34,28 JDIGITAL1.10
  S3 w0.064: v3(17.81,5.01) 18.01,5.01 v2(18.12,4.9)
  S6 w0.064: v4(12.45,17.81) 11.56,16.92 11.56,15.27 17.11,9.72 17.11,6.27 17.81,5.57 v3(17.81,5.01)
  G7 w0.064: v5(12.65,19.76) 12.65,19.56 12.41,19.32 12.41,17.84 v4(12.45,17.81)
  BOTTOM w0.051: MCU1.E5 12.65,23.36 12.65,21.21
  BOTTOM w0.066: v5(12.65,19.76) 12.75,19.86 12.75,20.65 12.57,20.83 12.57,21.13 12.65,21.21
MCU_PC0: length 23.1
  G7 w0.064: v5(5.84,21.23) 6.25,21.65 10.72,21.65 10.9,21.82 v5(10.9,22.11)
  BOTTOM w0.058: v5(5.84,21.23) 5.31,20.7 5.31,12.6 4.11,11.4 4.11,9.4 3.76,9.04 3.76,6.3 JANALOG1.14
MCU_PC1: length 21.3
  G7 w0.064: v5(5.44,21.21) 6.36,22.13 8.04,22.13 8.35,21.82 10.46,21.82 10.61,21.97 10.61,22.33 v5(10.9,22.61)
  BOTTOM w0.058: JANALOG1.13 2.54,8.08 3.96,9.5 3.96,11.56 5.16,12.75 5.16,20.93 v5(5.44,21.21)
MCU_PE7: length 65
  G7 w0.064: v5(18.82,9.82) 18.76,9.76 18.76,7.4 18.29,6.93 18.29,6.28 17.81,5.8 3.99,5.8 3.74,6.05 3.74,13.42 4.04,13.72 4.04,18.15 3,19.19 3,21.62 4.12,22.74 v5(4.12,22.95)
  BOTTOM w0.058: 6.49,23.17 7.11,23.79 7.69,23.79 ; MCU1.L7 9.65,24.86 8.76,24.86
  BOTTOM w0.066: v5(4.12,22.95) 4.43,22.64 4.98,22.64 5.51,23.17 6.49,23.17 ; 7.69,23.79 8.76,24.86 ; v5(18.82,9.82) 19.14,10.14 38.1,10.14 38.73,10.77 38.73,11.98
MCU_PE8: length 64.2
  G7 w0.064: v5(18.65,10.13) 18.62,10.1 18.62,7.46 18.15,6.99 18.15,6.34 17.75,5.94 4.08,5.94 3.87,6.15 3.87,13.37 4.17,13.67 4.17,18.2 3.13,19.24 3.13,21.57 4.46,22.9 v5(4.46,22.95)
  BOTTOM w0.058: 5.17,23.12 5.37,23.32 6.44,23.32 7.05,23.93 7.54,23.93 8.62,25.01 8.62,25.29 8.68,25.35 10,25.35 10.14,25.21 10.14,24.96 10.4,24.7 MCU1.K7
  BOTTOM w0.066: v5(4.46,22.95) 4.63,23.12 5.17,23.12 ; 37.46,11.98 37.46,11.04 36.71,10.29 18.81,10.29 v5(18.65,10.13)
MCU_PSSI_D0: length 49.5
  S6 w0.064: v5(13.16,27.38) 12.9,27.13 12.9,26.44 13.16,26.19 13.16,21.67 13.82,21.01 13.82,17.42 16.02,15.22 16.02,13.67 23.04,6.65 43.57,6.65 45,8.08 v5(45.08,8.08)
  BOTTOM w0.051: MCU1.H13 11.63,27.38 v5(13.16,27.38)
MCU_PSSI_D1: length 46.7
  S6 w0.064: v5(13.15,26.86) 13.31,26.7 13.31,21.74 13.97,21.08 13.97,17.5 16.15,15.32 16.15,13.77 23.09,6.83 42.48,6.83 43.73,8.08 v5(43.81,8.08)
  BOTTOM w0.051: v5(13.15,26.86) 12.15,26.86 MCU1.G12
MCU_PSSI_D2: length 44.6
  S6 w0.064: v4(13.61,25.91) 13.49,25.78 13.49,21.81 14.15,21.15 14.15,17.58 16.28,15.44 16.28,13.83 23.07,7.04 41.41,7.04 42.46,8.08 v5(42.54,8.08)
  G7 w0.064: v4(13.61,25.91) 12.1,25.91 v5(11.9,26.11)
MCU_PSSI_D3: length 42.9
  S6 w0.064: v4(13.85,25.53) 13.87,25.53 13.64,25.3 13.64,21.95 14.35,21.23 14.35,17.58 16.42,15.51 16.42,13.9 23.11,7.21 40.31,7.21 41.19,8.08 v5(41.27,8.08)
  G7 w0.064: v4(13.85,25.53) 13.87,25.53 13.87,25.53 13.78,25.61 v5(11.9,25.61)
MCU_PSSI_D4: length 35.7
  S6 w0.064: v5(13.89,22.1) 13.9,22.1 13.9,22.07 14.53,21.44 14.53,17.63 16.54,15.62 16.54,13.99 23.19,7.34 39.18,7.34 39.92,8.08 v5(40,8.08)
MCU_PSSI_D5: length 38.9
  S6 w0.05: 38.36,7.62 38.22,7.48 34.36,7.48
  S6 w0.064: v5(38.73,7.91) 38.65,7.91 38.36,7.62 ; v5(14.17,26.34) 14.12,26.29 14.12,26.22 14.13,26.21 14.13,26.02 14.08,25.97 14.08,25.85 14.08,25.85 14.08,25.62 14.08,25.43 13.89,25.24 13.89,22.4 13.95,22.35 13.98,22.35 14.13,22.19 14.13,22.16 14.73,21.56 14.73,17.65 16.68,15.71 16.68,14.06 23.25,7.48 34.36,7.48
  BOTTOM w0.051: MCU1.B10 14.17,26.32 v5(14.17,26.34)
MCU_PSSI_D6: length 32.2
  S6 w0.064: v5(37.46,7.91) 37.18,7.62 23.31,7.62 16.83,14.1 16.83,15.78 14.94,17.68 14.94,22.08 v5(14.9,22.11)
MCU_PSSI_D7: length 32.5
  S6 w0.064: v4(36.2,8.13) 35.83,7.76 23.36,7.76 16.97,14.15 16.97,15.9 15.13,17.74 15.13,22.2 14.9,22.43 14.23,22.43 v4(14.22,22.43)
  G7 w0.064: v4(36.2,8.13) 36.19,8.13 v5(36.19,7.91) ; v5(13.9,22.61) 14.02,22.49 14.16,22.49 v4(14.22,22.43)
MCU_PSSI_DE: length 72.9
  S6 w0.064: v5(15.63,2.91) 14.98,2.91 14.89,3 11.02,3 8.99,5.03 5.71,5.03 4.53,3.85 1.97,3.85 1.1,4.71 1.1,26.38 1.32,26.59 v4(1.7,26.59)
  G7 w0.064: v4(1.7,26.59) 3.89,26.59 5.13,27.84 8.81,27.84 9.25,27.41 9.75,27.41 v5(9.91,27.25)
  BOTTOM w0.066: v5(9.91,27.25) 9.9,27.25 MCU1.L12 ; JMISC1.21 32.21,7.91 32.21,2.03 31.35,1.17 24.37,1.17 24.1,1.44 24.1,2.99 23.55,3.54 16.26,3.54 v5(15.63,2.91)
MCU_PSSI_PDCK: length 75.1
  S6 w0.064: v5(15.61,2.54) 15.13,2.54 14.82,2.85 10.9,2.85 9,4.75 5.68,4.75 4.6,3.67 1.89,3.67 0.93,4.64 0.93,26.45 1.42,26.95 v4(1.68,26.95)
  G7 w0.064: v5(9.9,27.61) 9.24,27.61 8.86,27.99 5.07,27.99 3.82,26.75 1.98,26.75 1.78,26.95 v4(1.68,26.95)
  BOTTOM w0.066: v5(15.61,2.54) 16.43,3.36 23.44,3.36 23.87,2.93 23.87,1.41 24.49,0.79 31.57,0.79 32.64,1.85 32.64,4.14 34.16,5.66 34.16,6.71 34.92,7.47 JMISC1.17
MCU_PSSI_RDY: length 35.7
  S6 w0.064: v4(12.88,22.78) 12.93,22.73 12.93,22.28 12.88,22.23 12.88,17.71 13.99,16.6 14.36,16.6 15.81,15.15 15.81,13.69 23.01,6.49 32.91,6.49 v5(33.65,5.75)
  G7 w0.064: v5(14.2,22.81) 14.15,22.86 12.95,22.86 v4(12.88,22.78)
  BOTTOM w0.066: MCU1.B3 v5(14.2,22.81) ; JMISC1.19 v5(33.65,5.75)
MCU_SDMMC1_CMD_PD2: length 73
  S6 w0.064: v4(14.3,4.43) 14.25,4.38 13.21,4.38 12.29,5.3 9.39,5.3 9.13,5.56 6.17,5.56 4.83,6.9 4.83,14.68 4.06,15.45 4.06,24 4.34,24.28 v4(4.47,24.28)
  G7 w0.064: v5(12.4,24.61) 12.22,24.43 9.65,24.43 9.4,24.18 7.76,24.18 7.5,23.93 6.38,23.93 6.02,24.28 v4(4.47,24.28) ; v5(20.45,9.09) 20.31,8.95 20.31,6.01 18.87,4.57 14.44,4.57 v4(14.3,4.43)
  BOTTOM w0.066: v5(20.45,9.09) 20.51,9.15 41.74,9.15 43.34,10.75 44.76,10.75 45.08,11.07 JMISC1.2
MCU_SOC_LPUART1_CTS: length 4.8
  G7 w0.064: v5(6.62,24.83) 6.85,24.6 7.88,24.6 8.89,25.61 v5(10.9,25.61)
MCU_SOC_LPUART1_RTS: length 4.9
  G7 w0.064: v5(11.4,26.11) 8.98,26.11 8.61,26.48 7.47,26.48 6.96,27 v5(6.96,27.05)
MCU_SOC_LPUART1_RX: length 4.6
  G7 w0.064: v5(11.4,25.61) 11.15,25.86 7.11,25.86 v5(6.96,26.01)
MCU_SOC_LPUART1_TX: length 5.2
  G7 w0.064: v5(7.14,24.36) 7.24,24.46 8.03,24.46 8.89,25.32 11.69,25.32 v5(11.9,25.11)
MCU_SPI2_CLK: length 1.6
  BOTTOM w0.051: 8.46,28.05 MCU1.N13
  BOTTOM w0.066: R2641.1 8.46,28.05
MCU_SPI2_CLK_CONN: length 104.2
  TOP w0.058: 11.99,4.28 v2(11.99,5.84) ; 24.23,7.01 48.54,7.01 48.74,7.21 48.74,37.56 JDIGITAL1.14
  TOP w0.066: 24.23,7.01 22.85,5.64 17.77,5.64 15.82,3.68 12.59,3.68 11.99,4.28
  S3 w0.064: v2(11.99,5.84) 11.99,6.31 12.11,6.43 v3(12.27,6.43)
  S6 w0.064: v3(12.27,6.43) 12.24,6.43 10.74,7.93 8.75,7.93 5.99,10.69 5.99,15.09 5.18,15.9 5.18,19.68 6.02,20.52 6.02,22 5.54,22.48 5.54,23.75 5.74,23.95 5.74,28.26 5.8,28.32 v5(5.82,28.32)
  BOTTOM w0.066: v5(5.82,28.32) 5.82,28.7 6.31,29.19 6.99,29.19 7.41,29.61 8.34,29.61 R2641.2
MCU_SPI2_CLK_PD1: length 54.3
  TOP w0.066: v2(18.4,4.72) 18.9,4.22 R2617.1
  S3 w0.064: v2(18.4,4.72) 18.4,5.04 18.03,5.41 14.11,5.41 12.45,7.07 8.35,7.07 6.45,5.17 5.77,5.17 4.32,3.72 1.77,3.72 0.71,4.78 0.71,10.04 0.71,10.05 0.71,22.81 v3(1.96,24.05)
  S6 w0.064: v3(1.96,24.05) 2.21,24.05 v4(2.26,24.1)
  G7 w0.064: v5(12.4,24.11) 12.2,24.31 9.7,24.31 9.44,24.04 7.82,24.04 7.56,23.79 4.58,23.79 4.27,24.1 v4(2.26,24.1)
MCU_SPI2_CLK_PD1_CONN: length 7
  TOP w0.058: 26.75,3.71 JSPI1.3
  TOP w0.066: R2617.2 22.28,4.22 22.79,3.71 26.75,3.71
MCU_SPI2_MISO: length 2
  BOTTOM w0.051: 9.14,28.83 9.14,27.37 MCU1.M12
  BOTTOM w0.066: 9.14,28.83 R2640.1
MCU_SPI2_MISO_CONN: length 102.7
  TOP w0.058: 11.71,4.31 v2(11.71,5.49) ; JDIGITAL1.13 48.88,35.16 48.88,7.15 48.56,6.83 24.3,6.83
  TOP w0.066: 24.3,6.83 22.93,5.46 17.85,5.46 15.9,3.51 12.51,3.51 11.71,4.31
  S3 w0.064: v2(11.71,5.49) 11.71,5.71 11.48,5.94 v3(11.48,6.45)
  S6 w0.064: v3(11.48,6.45) 11.48,6.64 10.35,7.78 8.72,7.78 5.83,10.67 5.83,15.03 5.02,15.83 5.02,19.73 5.87,20.57 5.87,21.92 5.38,22.4 5.38,23.81 5.59,24.02 5.59,28.17 v5(5.46,28.3)
  BOTTOM w0.066: v5(5.46,28.3) 5.49,28.32 5.49,28.85 6.03,29.4 6.94,29.4 7.35,29.8 8.68,29.8 R2640.2
MCU_SPI2_MISO_PC2: length 37.9
  TOP w0.058: v2(10.02,5.42) 10.02,5.19 12.24,2.97 17.59,2.97
  TOP w0.066: R2618.1 20.51,2.97 17.59,2.97
  S3 w0.064: v2(10.02,5.42) 10.01,5.42 v3(8.68,6.75)
  S6 w0.064: v3(8.68,6.75) 8.54,6.75 7.83,7.46 v5(5.7,7.46)
  BOTTOM w0.058: 6.3,22.23 7.9,22.23 8.53,22.86
  BOTTOM w0.066: 6.3,22.23 6.1,22.02 6.1,21.01 5.51,20.42 5.51,10.16 5.73,9.94 5.73,7.49 v5(5.7,7.46) ; MCU1.J4 10.65,22.86 8.53,22.86
MCU_SPI2_MISO_PC2_CONN: length 9.4
  TOP w0.058: JSPI1.1 29.15,3.57 22.72,3.57
  TOP w0.066: R2618.2 21.7,3.57 22.72,3.57
MCU_SPI2_MOSI: length 4.3
  G7 w0.064: v5(9.55,28.5) 7.62,28.5 v5(7.37,28.75)
  BOTTOM w0.066: MCU1.L11 9.65,26.86 9.65,28.4 v5(9.55,28.5)
MCU_SPI2_MOSI_CONN: length 97.8
  TOP w0.058: 24.36,6.68 48.62,6.68 49.03,7.1 49.03,32.77 JDIGITAL1.12 ; v2(11.2,5.49) 11.2,4.52 12.37,3.35
  TOP w0.066: 24.36,6.68 22.99,5.31 17.91,5.31 15.96,3.35 12.37,3.35
  S3 w0.064: v3(10.85,6.72) 11.02,6.55 11.02,5.66 v2(11.2,5.49)
  S6 w0.064: v5(6.12,28.63) 6.1,28.65 5.31,28.65 5.21,28.55 5.21,22.33 5.71,21.82 5.71,20.62 4.86,19.76 4.86,15.77 5.66,14.96 5.66,10.65 8.69,7.62 9.83,7.62 10.73,6.72 v3(10.85,6.72)
  BOTTOM w0.066: R2626.2 6.2,28.75 6.12,28.68 v5(6.12,28.63)
MCU_SPI2_MOSI_PC3: length 34.6
  TOP w0.058: v2(9.88,5.82) 9.78,5.71 9.78,5.13 12.14,2.77 17.68,2.77
  TOP w0.066: R2619.1 20.91,2.77 17.68,2.77
  S3 w0.064: v3(9.46,6.69) 9.88,6.27 v2(9.88,5.82)
  S6 w0.064: v5(6.46,9.47) 6.46,9.23 6.79,8.9 6.96,8.9 8.55,7.31 8.84,7.31 v3(9.46,6.69)
  BOTTOM w0.058: MCU1.K1 10.17,21.84 9.26,21.84 9.15,21.73 ; 9.15,21.37 8.83,21.05 8.59,21.05 8.21,20.67
  BOTTOM w0.066: 9.15,21.37 9.15,21.73 ; 8.21,20.67 7.03,20.67 6.48,20.12 6.48,19.57 6.04,19.13 6.04,17.76 5.84,17.56 5.84,10.45 6.46,9.83 v5(6.46,9.47)
MCU_SPI2_MOSI_PC3_CONN: length 7.6
  TOP w0.066: JSPI1.4 27.95,2.35 26.7,1.09 23.95,1.09 22.07,2.98 R2619.2
MCU_SPI2_NSS: length 9.4
  G7 w0.064: v5(13.87,20.95) 13,20.09 8.36,20.09 8.03,19.76 v5(7.8,19.76)
  BOTTOM w0.051: MCU1.D5 13.64,23.37
  BOTTOM w0.066: v5(13.87,20.95) 13.64,21.18 13.64,23.37
MCU_SPI2_NSS_CONN: length 84
  TOP w0.058: 10.72,4.8 v2(10.72,5.41) ; 24.43,6.51 48.65,6.51 49.18,7.04 49.18,30.38 JDIGITAL1.11
  TOP w0.066: 24.43,6.51 23.06,5.14 17.98,5.14 15.98,3.14 12.38,3.14 10.72,4.8
  S3 w0.064: v2(10.72,5.41) 10.44,5.69 10.44,6.43 v3(10.16,6.71)
  S6 w0.064: v3(10.16,6.71) 9.42,7.44 8.67,7.44 6.83,9.28 v5(6.73,9.28)
  BOTTOM w0.066: R2625.2 6.05,17.5 6.05,10.49 6.73,9.81 v5(6.73,9.28)
MCU_SPI3_CLK: length 13.6
  S3 w0.05: v2(27.37,28.88) 27.37,28.68
  S3 w0.064: 27.37,28.68 25.99,27.3 22.53,27.3 22,26.77 19.13,26.77 v3(19.02,26.67)
  S6 w0.064: v3(19.02,26.67) 19,26.64 v5(18.72,26.64)
  BOTTOM w0.066: v5(18.72,26.64) 18.72,24.97 18.34,24.59 17.17,24.59 17.09,24.66 R2505.2
MCU_SPI3_CLK_R: length 1.3
  BOTTOM w0.051: 16.13,24.66 14.95,24.66 MCU1.A7
MCU_SPI3_CS_N: length 37.6
  TOP w0.066: v2(25.55,17.73) 25.33,17.95 25.33,22.52 26.45,23.64 26.45,24.75 27.37,25.67 SOC1.AA30
  S3 w0.066: v2(25.55,17.73) 25.45,17.63 21.49,17.63 19.67,15.81 18.71,15.81 18.34,15.44 11.98,15.44 11.29,16.13 6.3,16.13 v3(6.05,15.88)
  S6 w0.064: v5(6.27,19.03) 6.27,16.1 v3(6.05,15.88)
  BOTTOM w0.066: v5(6.27,19.03) 6.68,19.44 6.68,19.95 7.04,20.31 R2508.2
MCU_SPI3_CS_N_R: length 15.2
  S6 w0.064: v4(4.32,21.18) 4.32,23.62 v4(4.34,23.65)
  G7 w0.064: v4(4.32,21.18) 4.52,20.98 5.11,20.98 5.31,20.78 7.34,20.78 v5(7.75,20.37) ; v5(12.9,24.11) 12.69,23.9 11.23,23.9 10.93,24.19 9.78,24.19 9.49,23.9 7.87,23.9 7.62,23.65 v4(4.34,23.65)
MCU_SPI3_MISO: length 40.7
  TOP w0.05: 28.17,28.33 28.17,28.48
  TOP w0.066: v2(25.56,18.03) 25.61,18.08 25.61,22.42 28.17,24.97 28.17,28.33
  S3 w0.064: v3(14.25,27.05) v3(18.69,27.05)
  S3 w0.066: v3(17.91,16.05) 18.39,16.05 18.95,16.61 20.19,16.61 21.36,17.78 25.12,17.78 25.37,18.03 v2(25.56,18.03)
  S6 w0.064: v3(17.91,16.05) 17.04,16.05 15.29,17.81 15.29,22.33 14.58,23.04 14.58,24.92 14.22,25.28 14.22,25.68 14.22,25.68 14.22,25.91 14.43,26.12 14.43,26.87 v3(14.25,27.05) ; v3(18.69,27.05) 18.62,27.13 v5(18.62,27.36)
  BOTTOM w0.066: v5(18.62,27.36) 18.39,27.13 18.39,25.27 R2506.2
MCU_SPI3_MISO_R: length 3.8
  BOTTOM w0.051: 15.65,24.84 14.13,24.84 MCU1.C7
  BOTTOM w0.066: 15.65,24.84 15.82,25.02 16.81,25.02 16.92,24.92 R2506.1
MCU_SPI3_MOSI_1P8V: length 26.1
  S3 w0.064: v2(27.77,28.91) 27.77,28.6 26.17,27 22.73,27 21.89,26.16 14.96,26.16 v3(14.53,25.73)
  S6 w0.064: v3(14.53,25.73) 14.63,25.83 14.63,29.35 14.41,29.57 v5(14.41,32.48)
  BOTTOM w0.066: U1102.3 18.04,33.51 17.58,33.05 14.98,33.05 v5(14.41,32.48)
MCU_SPI3_MOSI_3P3V: length 13.3
  G7 w0.064: v5(19.64,30.69) 19.68,30.64 19.68,28.78 19.86,28.6 19.86,22.85 19.57,22.56 v5(19.17,22.56)
  BOTTOM w0.066: U1102.4 18.04,31.18 18.53,30.69 v5(19.64,30.69) ; v5(19.17,22.56) 19.11,22.56 18.76,22.91 R2507.1
MCU_SPI3_MOSI_R: length 2.9
  BOTTOM w0.051: MCU1.C6 14.13,23.88 15.37,23.88
  BOTTOM w0.066: 15.37,23.88 R2507.2
MCU_SPI3_RDY: length 44
  S3 w0.05: v2(28.17,28.88) 28.17,28.56 27.94,28.33
  S3 w0.064: 27.94,28.33 26.31,26.7 22.83,26.7 21.96,25.83 17.92,25.83 15.92,23.83 15.92,17.51 15.32,16.91 6.68,16.91 6.43,17.17 6.02,17.17 v3(5.84,17.35)
  S6 w0.064: v3(5.84,17.35) 5.84,19.25 v4(5.77,19.33)
  G7 w0.064: v4(5.77,19.33) v5(4.22,19.33)
  BOTTOM w0.058: v5(4.22,19.33) 4.27,19.38 4.27,21.87
  BOTTOM w0.066: 4.27,21.87 3.81,22.33 3.81,23.78 5.57,25.54 5.57,26.24 6.15,26.83 R2516.2
MCU_SPI3_RDY_R: length 3.1
  BOTTOM w0.066: MCU1.N10 8.47,25.68 6.66,25.68 6.52,25.82 R2516.1
MCU_TRACE_CLK: length 43.6
  S6 w0.064: v4(12.59,17.05) 11.86,16.32 11.86,15.37 17.91,9.32 v5(17.91,9.15)
  G7 w0.064: v4(12.59,17.05) 12.7,17.16 12.7,19.38 14.9,21.58 v5(14.9,21.61)
  BOTTOM w0.066: v5(17.91,9.15) 18.07,9.31 41.65,9.31 43.81,11.48 JMISC1.4
